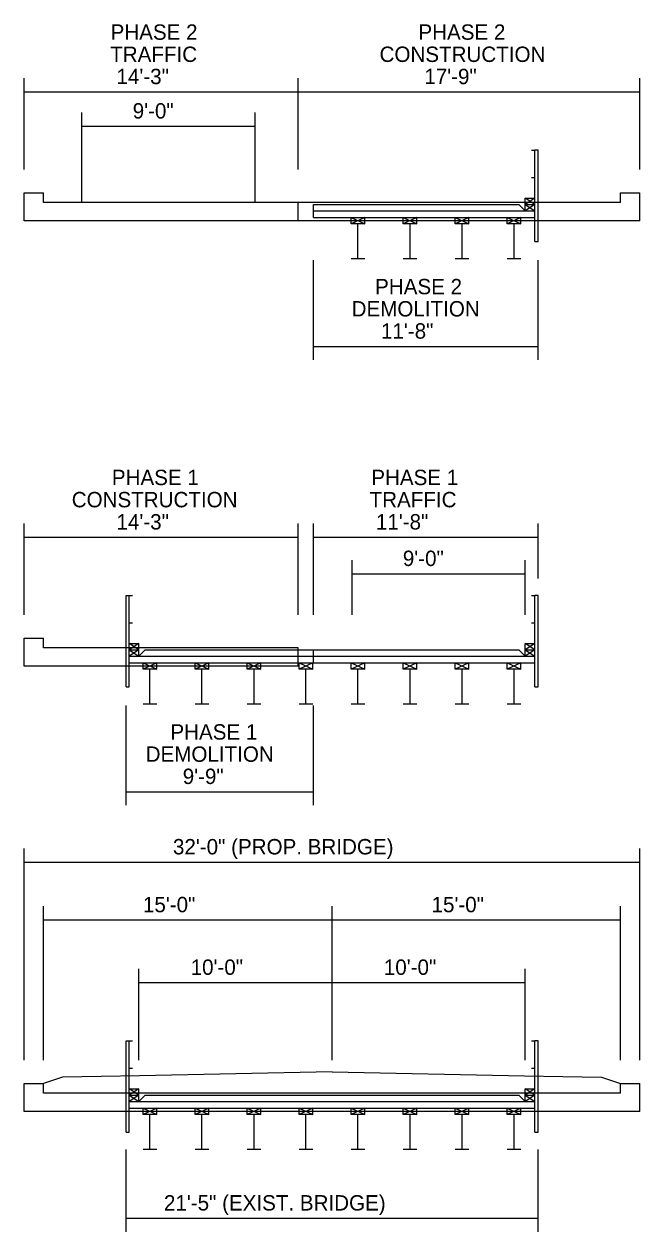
# Model space of a CAD drawing. Extents: x -452 to 3103, y -29 to 1600.
# Drawn here: x -169.2 to -137.2, y 1536.9 to 1599.7 of the extents above; entities that cross this region are included whole.
import ezdxf

# ---------------------------------------------------------------- set-up
doc = ezdxf.new("R2010")
doc.units = 0
doc.layers.add('DESIGN - SCRATCH - User 1', color=7, linetype='Continuous')

msp = doc.modelspace()

# ---------------------------------------------------------------- linework, layer by layer
at = {"layer": 'DESIGN - SCRATCH - User 1'}
for p, q in [((-169.218, 1592.159), (-169.218, 1596.906)), ((-154.968, 1592.159), (-154.968, 1596.906)), ((-137.218, 1592.159), (-137.218, 1596.906)), ((-169.218, 1596.194), (-154.968, 1596.194)), ((-154.968, 1596.194), (-137.218, 1596.194)), ((-166.218, 1590.445), (-166.218, 1595.116)), ((-157.218, 1590.445), (-157.218, 1595.116)), ((-166.218, 1594.406), (-157.218, 1594.406)), ((-142.845, 1593.169), (-142.678, 1593.169)), ((-142.678, 1588.42), (-142.678, 1593.169)), ((-142.511, 1593.169), (-142.678, 1593.169)), ((-142.511, 1588.42), (-142.511, 1593.169)), ((-142.845, 1591.749), (-142.678, 1591.749)), ((-169.218, 1589.485), (-169.218, 1590.945)), ((-169.218, 1590.945), (-168.218, 1590.945)), ((-168.218, 1590.445), (-168.218, 1590.945)), ((-143.178, 1590.002), (-143.178, 1590.669)), ((-143.178, 1590.669), (-142.678, 1590.669)), ((-142.678, 1590.335), (-143.178, 1590.669)), ((-142.678, 1590.669), (-143.178, 1590.335)), ((-138.218, 1590.445), (-138.218, 1590.945)), ((-138.218, 1590.945), (-137.218, 1590.945)), ((-137.218, 1589.485), (-137.218, 1590.945)), ((-154.968, 1590.445), (-168.218, 1590.445)), ((-154.968, 1589.485), (-154.968, 1590.445)), ((-138.218, 1590.445), (-154.968, 1590.445)), ((-154.178, 1590.335), (-143.511, 1590.335)), ((-154.178, 1589.669), (-154.178, 1590.335)), ((-154.178, 1590.002), (-142.678, 1590.002)), ((-143.178, 1590.002), (-143.511, 1590.335)), ((-143.178, 1590.335), (-142.678, 1590.335)), ((-143.178, 1590.335), (-142.678, 1590.002)), ((-142.678, 1590.335), (-143.178, 1590.002)), ((-154.968, 1589.485), (-169.218, 1589.485)), ((-137.218, 1589.485), (-154.968, 1589.485)), ((-154.178, 1589.669), (-142.678, 1589.669)), ((-152.227, 1589.335), (-152.227, 1589.669)), ((-151.507, 1589.669), (-152.227, 1589.335)), ((-152.227, 1589.669), (-151.507, 1589.335)), ((-151.507, 1589.335), (-152.227, 1589.335)), ((-151.867, 1587.505), (-151.867, 1589.335)), ((-151.507, 1589.335), (-151.507, 1589.669)), ((-149.524, 1589.335), (-149.524, 1589.669)), ((-148.804, 1589.669), (-149.524, 1589.335)), ((-149.524, 1589.669), (-148.804, 1589.335)), ((-148.804, 1589.335), (-149.524, 1589.335)), ((-149.164, 1587.505), (-149.164, 1589.335)), ((-148.804, 1589.335), (-148.804, 1589.669)), ((-146.821, 1589.335), (-146.821, 1589.669)), ((-146.101, 1589.669), (-146.821, 1589.335)), ((-146.821, 1589.669), (-146.101, 1589.335)), ((-146.101, 1589.335), (-146.821, 1589.335)), ((-146.461, 1587.505), (-146.461, 1589.335)), ((-146.101, 1589.335), (-146.101, 1589.669)), ((-144.118, 1589.335), (-144.118, 1589.669)), ((-143.398, 1589.669), (-144.118, 1589.335)), ((-144.118, 1589.669), (-143.398, 1589.335)), ((-143.398, 1589.335), (-144.118, 1589.335)), ((-143.758, 1587.505), (-143.758, 1589.335)), ((-143.398, 1589.335), (-143.398, 1589.669)), ((-142.678, 1588.42), (-142.511, 1588.42)), ((-154.178, 1582.253), (-154.178, 1587.441)), ((-151.507, 1587.505), (-152.227, 1587.505)), ((-148.804, 1587.505), (-149.524, 1587.505)), ((-146.101, 1587.505), (-146.821, 1587.505)), ((-143.398, 1587.505), (-144.118, 1587.505)), ((-142.511, 1582.253), (-142.511, 1587.441)), ((-154.178, 1582.961), (-142.511, 1582.961)), ((-169.218, 1569.003), (-169.218, 1573.75)), ((-154.968, 1569.003), (-154.968, 1573.75)), ((-154.178, 1569.003), (-154.178, 1573.75)), ((-142.511, 1570.896), (-142.511, 1573.75)), ((-169.218, 1573.038), (-154.968, 1573.038)), ((-154.178, 1573.038), (-142.511, 1573.038)), ((-152.178, 1569.003), (-152.178, 1571.849)), ((-143.178, 1569.003), (-143.178, 1571.849)), ((-152.178, 1571.139), (-143.178, 1571.139)), ((-163.925, 1565.264), (-163.925, 1570.012)), ((-163.925, 1570.012), (-163.758, 1570.012)), ((-163.758, 1565.264), (-163.758, 1570.012)), ((-163.758, 1570.012), (-163.591, 1570.012)), ((-142.845, 1570.012), (-142.678, 1570.012)), ((-142.678, 1565.264), (-142.678, 1570.012)), ((-142.511, 1570.012), (-142.678, 1570.012)), ((-142.511, 1565.264), (-142.511, 1570.012)), ((-163.758, 1568.592), (-163.591, 1568.592)), ((-142.845, 1568.592), (-142.678, 1568.592)), ((-169.218, 1566.329), (-169.218, 1567.789)), ((-169.218, 1567.789), (-168.218, 1567.789)), ((-168.218, 1567.289), (-168.218, 1567.789)), ((-163.758, 1567.512), (-163.258, 1567.512)), ((-163.258, 1567.179), (-163.758, 1567.512)), ((-163.258, 1567.512), (-163.758, 1567.179)), ((-163.258, 1566.846), (-163.258, 1567.512)), ((-143.178, 1566.846), (-143.178, 1567.512)), ((-143.178, 1567.512), (-142.678, 1567.512)), ((-142.678, 1567.179), (-143.178, 1567.512)), ((-142.678, 1567.512), (-143.178, 1567.179)), ((-154.968, 1567.289), (-168.218, 1567.289)), ((-163.758, 1567.179), (-163.258, 1567.179)), ((-163.758, 1567.179), (-163.258, 1566.846)), ((-163.258, 1567.179), (-163.758, 1566.846)), ((-163.758, 1566.846), (-142.678, 1566.846)), ((-163.258, 1566.846), (-162.925, 1567.179)), ((-162.925, 1567.179), (-143.511, 1567.179)), ((-154.968, 1566.329), (-154.968, 1567.289)), ((-154.178, 1566.512), (-154.178, 1567.179)), ((-143.178, 1566.846), (-143.511, 1567.179)), ((-143.178, 1567.179), (-142.678, 1567.179)), ((-143.178, 1567.179), (-142.678, 1566.846)), ((-142.678, 1567.179), (-143.178, 1566.846)), ((-154.968, 1566.329), (-169.218, 1566.329)), ((-163.758, 1566.512), (-142.678, 1566.512)), ((-163.038, 1566.179), (-163.038, 1566.512)), ((-162.318, 1566.512), (-163.038, 1566.179)), ((-163.038, 1566.512), (-162.318, 1566.179)), ((-162.318, 1566.179), (-163.038, 1566.179)), ((-162.678, 1564.349), (-162.678, 1566.179)), ((-162.318, 1566.179), (-162.318, 1566.512)), ((-160.335, 1566.179), (-160.335, 1566.512)), ((-159.615, 1566.512), (-160.335, 1566.179)), ((-160.335, 1566.512), (-159.615, 1566.179)), ((-159.615, 1566.179), (-160.335, 1566.179)), ((-159.975, 1564.349), (-159.975, 1566.179)), ((-159.615, 1566.179), (-159.615, 1566.512)), ((-157.632, 1566.179), (-157.632, 1566.512)), ((-156.912, 1566.512), (-157.632, 1566.179)), ((-157.632, 1566.512), (-156.912, 1566.179)), ((-156.912, 1566.179), (-157.632, 1566.179)), ((-157.272, 1564.349), (-157.272, 1566.179)), ((-156.912, 1566.179), (-156.912, 1566.512)), ((-154.93, 1566.179), (-154.93, 1566.512)), ((-154.21, 1566.512), (-154.93, 1566.179)), ((-154.93, 1566.512), (-154.21, 1566.179)), ((-154.21, 1566.179), (-154.93, 1566.179)), ((-154.57, 1564.349), (-154.57, 1566.179)), ((-154.21, 1566.179), (-154.21, 1566.512)), ((-152.227, 1566.179), (-152.227, 1566.512)), ((-151.507, 1566.512), (-152.227, 1566.179)), ((-152.227, 1566.512), (-151.507, 1566.179)), ((-151.507, 1566.179), (-152.227, 1566.179)), ((-151.867, 1564.349), (-151.867, 1566.179)), ((-151.507, 1566.179), (-151.507, 1566.512)), ((-149.524, 1566.179), (-149.524, 1566.512)), ((-148.804, 1566.512), (-149.524, 1566.179)), ((-149.524, 1566.512), (-148.804, 1566.179)), ((-148.804, 1566.179), (-149.524, 1566.179)), ((-149.164, 1564.349), (-149.164, 1566.179)), ((-148.804, 1566.179), (-148.804, 1566.512)), ((-146.821, 1566.179), (-146.821, 1566.512)), ((-146.101, 1566.512), (-146.821, 1566.179)), ((-146.821, 1566.512), (-146.101, 1566.179)), ((-146.101, 1566.179), (-146.821, 1566.179)), ((-146.461, 1564.349), (-146.461, 1566.179)), ((-146.101, 1566.179), (-146.101, 1566.512)), ((-144.118, 1566.179), (-144.118, 1566.512)), ((-143.398, 1566.512), (-144.118, 1566.179)), ((-144.118, 1566.512), (-143.398, 1566.179)), ((-143.398, 1566.179), (-144.118, 1566.179)), ((-143.758, 1564.349), (-143.758, 1566.179)), ((-143.398, 1566.179), (-143.398, 1566.512)), ((-163.925, 1565.264), (-163.758, 1565.264)), ((-142.678, 1565.264), (-142.511, 1565.264)), ((-163.925, 1559.097), (-163.925, 1564.284)), ((-162.318, 1564.349), (-163.038, 1564.349)), ((-159.615, 1564.349), (-160.335, 1564.349)), ((-156.912, 1564.349), (-157.632, 1564.349)), ((-154.21, 1564.349), (-154.93, 1564.349)), ((-154.178, 1559.097), (-154.178, 1564.284)), ((-151.507, 1564.349), (-152.227, 1564.349)), ((-148.804, 1564.349), (-149.524, 1564.349)), ((-146.101, 1564.349), (-146.821, 1564.349)), ((-143.398, 1564.349), (-144.118, 1564.349)), ((-163.925, 1559.805), (-154.178, 1559.805)), ((-169.218, 1545.847), (-169.218, 1556.857)), ((-137.218, 1545.847), (-137.218, 1556.857)), ((-169.218, 1556.145), (-137.218, 1556.145)), ((-168.218, 1545.847), (-168.218, 1553.849)), ((-153.218, 1545.847), (-153.218, 1553.849)), ((-138.218, 1545.847), (-138.218, 1553.849)), ((-168.218, 1553.137), (-153.218, 1553.137)), ((-153.218, 1553.137), (-138.218, 1553.137)), ((-163.258, 1545.847), (-163.258, 1550.594)), ((-143.178, 1545.847), (-143.178, 1550.594)), ((-163.258, 1549.882), (-153.218, 1549.882)), ((-153.218, 1549.882), (-143.178, 1549.882)), ((-163.925, 1542.108), (-163.925, 1546.856)), ((-163.925, 1546.856), (-163.758, 1546.856)), ((-163.758, 1542.108), (-163.758, 1546.856)), ((-163.758, 1546.856), (-163.591, 1546.856)), ((-142.845, 1546.856), (-142.678, 1546.856)), ((-142.678, 1542.108), (-142.678, 1546.856)), ((-142.511, 1546.856), (-142.678, 1546.856)), ((-142.511, 1542.108), (-142.511, 1546.856)), ((-163.758, 1545.436), (-163.591, 1545.436)), ((-142.845, 1545.436), (-142.678, 1545.436)), ((-167.218, 1544.954), (-168.218, 1544.633)), ((-165.218, 1544.994), (-167.218, 1544.954)), ((-163.218, 1545.034), (-165.218, 1544.994)), ((-153.218, 1545.234), (-163.218, 1545.034)), ((-153.218, 1545.234), (-143.218, 1545.034)), ((-143.218, 1545.034), (-141.218, 1544.994)), ((-141.218, 1544.994), (-139.218, 1544.954)), ((-139.218, 1544.954), (-138.218, 1544.633)), ((-169.218, 1543.173), (-169.218, 1544.633)), ((-169.218, 1544.633), (-168.218, 1544.633)), ((-168.218, 1544.133), (-168.218, 1544.633)), ((-138.218, 1544.133), (-168.218, 1544.133)), ((-163.758, 1544.356), (-163.258, 1544.356)), ((-163.258, 1544.023), (-163.758, 1544.356)), ((-163.258, 1544.356), (-163.758, 1544.023)), ((-163.258, 1543.689), (-163.258, 1544.356)), ((-143.178, 1543.689), (-143.178, 1544.356)), ((-143.178, 1544.356), (-142.678, 1544.356)), ((-142.678, 1544.023), (-143.178, 1544.356)), ((-142.678, 1544.356), (-143.178, 1544.023)), ((-138.218, 1544.133), (-138.218, 1544.633)), ((-138.218, 1544.633), (-137.218, 1544.633)), ((-137.218, 1543.173), (-137.218, 1544.633)), ((-163.758, 1544.023), (-163.258, 1544.023)), ((-163.758, 1544.023), (-163.258, 1543.689)), ((-163.258, 1544.023), (-163.758, 1543.689)), ((-163.758, 1543.689), (-142.678, 1543.689)), ((-163.258, 1543.689), (-162.925, 1544.023)), ((-162.925, 1544.023), (-143.511, 1544.023)), ((-143.178, 1543.689), (-143.511, 1544.023)), ((-143.178, 1544.023), (-142.678, 1544.023)), ((-143.178, 1544.023), (-142.678, 1543.689)), ((-142.678, 1544.023), (-143.178, 1543.689)), ((-137.218, 1543.173), (-169.218, 1543.173)), ((-163.758, 1543.356), (-142.678, 1543.356)), ((-163.038, 1543.023), (-163.038, 1543.356)), ((-162.318, 1543.356), (-163.038, 1543.023)), ((-163.038, 1543.356), (-162.318, 1543.023)), ((-162.318, 1543.023), (-163.038, 1543.023)), ((-162.678, 1541.193), (-162.678, 1543.023)), ((-162.318, 1543.023), (-162.318, 1543.356)), ((-160.335, 1543.023), (-160.335, 1543.356)), ((-159.615, 1543.356), (-160.335, 1543.023)), ((-160.335, 1543.356), (-159.615, 1543.023)), ((-159.615, 1543.023), (-160.335, 1543.023)), ((-159.975, 1541.193), (-159.975, 1543.023)), ((-159.615, 1543.023), (-159.615, 1543.356)), ((-157.632, 1543.023), (-157.632, 1543.356)), ((-156.912, 1543.356), (-157.632, 1543.023)), ((-157.632, 1543.356), (-156.912, 1543.023)), ((-156.912, 1543.023), (-157.632, 1543.023)), ((-157.272, 1541.193), (-157.272, 1543.023)), ((-156.912, 1543.023), (-156.912, 1543.356)), ((-154.93, 1543.023), (-154.93, 1543.356)), ((-154.21, 1543.356), (-154.93, 1543.023)), ((-154.93, 1543.356), (-154.21, 1543.023)), ((-154.21, 1543.023), (-154.93, 1543.023)), ((-154.57, 1541.193), (-154.57, 1543.023)), ((-154.21, 1543.023), (-154.21, 1543.356)), ((-152.227, 1543.023), (-152.227, 1543.356)), ((-151.507, 1543.356), (-152.227, 1543.023)), ((-152.227, 1543.356), (-151.507, 1543.023)), ((-151.507, 1543.023), (-152.227, 1543.023)), ((-151.867, 1541.193), (-151.867, 1543.023)), ((-151.507, 1543.023), (-151.507, 1543.356)), ((-149.524, 1543.023), (-149.524, 1543.356)), ((-148.804, 1543.356), (-149.524, 1543.023)), ((-149.524, 1543.356), (-148.804, 1543.023)), ((-148.804, 1543.023), (-149.524, 1543.023)), ((-149.164, 1541.193), (-149.164, 1543.023)), ((-148.804, 1543.023), (-148.804, 1543.356)), ((-146.821, 1543.023), (-146.821, 1543.356)), ((-146.101, 1543.356), (-146.821, 1543.023)), ((-146.821, 1543.356), (-146.101, 1543.023)), ((-146.101, 1543.023), (-146.821, 1543.023)), ((-146.461, 1541.193), (-146.461, 1543.023)), ((-146.101, 1543.023), (-146.101, 1543.356)), ((-144.118, 1543.023), (-144.118, 1543.356)), ((-143.398, 1543.356), (-144.118, 1543.023)), ((-144.118, 1543.356), (-143.398, 1543.023)), ((-143.398, 1543.023), (-144.118, 1543.023)), ((-143.758, 1541.193), (-143.758, 1543.023)), ((-143.398, 1543.023), (-143.398, 1543.356)), ((-163.925, 1542.108), (-163.758, 1542.108)), ((-142.678, 1542.108), (-142.511, 1542.108)), ((-163.925, 1536.92), (-163.925, 1541.193)), ((-162.318, 1541.193), (-163.038, 1541.193)), ((-159.615, 1541.193), (-160.335, 1541.193)), ((-156.912, 1541.193), (-157.632, 1541.193)), ((-154.21, 1541.193), (-154.93, 1541.193)), ((-151.507, 1541.193), (-152.227, 1541.193)), ((-148.804, 1541.193), (-149.524, 1541.193)), ((-146.101, 1541.193), (-146.821, 1541.193)), ((-143.398, 1541.193), (-144.118, 1541.193)), ((-142.511, 1536.92), (-142.511, 1541.193)), ((-163.925, 1537.628), (-142.511, 1537.628))]:
    msp.add_line(p, q, dxfattribs=at)

# ---------------------------------------------------------------- texts
for s, p in [('PHASE 2', (-164.726, 1598.902)), ('PHASE 2', (-148.726, 1598.902)), ('TRAFFIC', (-164.746, 1597.748)), ('CONSTRUCTION', (-150.745, 1597.748)), ('14\'-3"', (-164.419, 1596.594)), ('17\'-9"', (-148.419, 1596.594)), ('9\'-0"', (-163.576, 1594.806)), ('PHASE 2', (-150.978, 1585.669)), ('DEMOLITION', (-152.197, 1584.515)), ('11\'-8"', (-150.671, 1583.361)), ('PHASE 1', (-164.66, 1575.746)), ('PHASE 1', (-151.177, 1575.746)), ('CONSTRUCTION', (-166.745, 1574.592)), ('TRAFFIC', (-151.264, 1574.592)), ('14\'-3"', (-164.419, 1573.438)), ('11\'-8"', (-150.936, 1573.438)), ('9\'-0"', (-149.536, 1571.539)), ('PHASE 1', (-161.617, 1562.513)), ('DEMOLITION', (-162.903, 1561.359)), ('9\'-9"', (-160.976, 1560.205)), ('32\'-0" (PROP. BRIDGE)', (-161.484, 1556.545)), ('15\'-0"', (-163.044, 1553.537)), ('15\'-0"', (-148.044, 1553.537)), ('10\'-0"', (-160.564, 1550.282)), ('10\'-0"', (-150.524, 1550.282)), ('21\'-5" (EXIST. BRIDGE)', (-161.952, 1538.028))]:
    msp.add_text(s, height=0.8, dxfattribs=at).set_placement(p)

doc.saveas('drawing.dxf')
